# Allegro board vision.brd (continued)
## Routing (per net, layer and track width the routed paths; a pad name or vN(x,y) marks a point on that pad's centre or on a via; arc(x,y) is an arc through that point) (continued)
MEMORY.RA8: length 228.6
  TOP w0.15: U5.66 68.44,104.04 69.4,105 69.4,107.86 69,108.26 69,109.5 69.4,109.9 70.5,109.9 ; v1(76.28,73.14) 73.04,73.14 71.14,75.04 71.14,85.08 70.1,86.11 70.1,87.7 71,88.6 71,109.4 70.5,109.9 ; v1(102.84,100.53) 102.84,102.01 U22.28 ; 70.5,109.9 70.5,113.1 70.66,113.25 v1(70.66,113.96) 73.7,117 75.13,117 75.88,116.25 75.88,114.13 75.2,113.45 75.2,112.51 77.12,110.59 77.12,108.16 78.42,106.86 78.42,104.27 79.06,103.63 U18.28 ; v1(102.7,87.1) 103.06,87.45 U21.28 ; U20.28 103.06,74.95 v1(102.4,74.3) 101.2,73.1 96.88,73.1 96.47,72.7 87.22,72.7 v1(86.14,73.78) ; U17.28 79.06,87.52 v1(78.83,87.3) ; U19.28 79.06,112.19 v1(79.28,111.97) ; U23.28 103.06,111.97 v1(102.54,111.46) ; U16.28 v1(79.06,74.55)
  BOTTOM w0.15: 81.06,74.55 81.83,73.78 v1(86.14,73.78) ; 81.06,74.55 81.6,75.09 81.6,82.3 81.17,82.73 78.83,82.73 ; 81.06,74.55 v1(79.06,74.55) ; v1(102.54,111.46) 103.1,110.9 103.1,101.5 102.84,101.24 v1(102.84,100.53) 102.84,99.82 103.1,99.56 103.1,88.21 102.7,87.81 v1(102.7,87.1) 102.7,84.14 103.6,83.24 103.6,79.06 102.4,77.86 v1(102.4,74.3) ; 78.83,82.73 v1(78.83,87.3) ; 78.83,82.73 78.44,82.73 76.1,80.39 76.1,74.02 76.28,73.85 v1(76.28,73.14) ; v1(79.28,111.97) 79.28,108.08 76.2,105 67.4,105 67,105.4 67,106.1 67.6,106.7 76.3,106.7 76.8,107.2 76.8,113.55 76.15,114.2 71.6,114.2 71.37,113.96 v1(70.66,113.96)
MEMORY.RA9: length 281.3
  TOP w0.15: U16.22 86.67,74.95 87.03,74.6 v1(88.28,74.6) ; U20.22 110.67,76.61 109.88,77.41 106.39,77.41 106.23,77.25 106.23,75.16 106.13,75.06 106.13,73.88 107.78,72.23 111.24,72.23 111.86,71.61 v1(116.1,71.61) ; U5.65 v1(68.91,102.77) ; U22.22 110.67,101.56 111.28,100.95 112.26,100.95 112.58,101.28 112.58,106.85 112.47,106.97 ; U19.22 v1(86.67,111.97) ; v1(87.1,86.1) 87.1,87.41 86.67,87.83 U17.22 86.67,90.48 86.45,90.7 81.96,90.7 80.96,91.71 80.96,93.86 81.08,93.97 81.08,95.67 v1(86,100.6) 86.67,101.28 U18.22 ; U23.22 110.67,115.61 111.47,116.41 112.34,116.41 112.58,116.16 112.58,114.14 112.47,114.03 112.47,106.97 ; 112.47,106.97 115.75,106.97 v1(116.49,107.7) 117.26,107.7 118.2,106.76 118.2,88.6 117.5,87.9 116.6,87.9 116.4,88.1 116.4,90.15 115.75,90.8 110.99,90.8 110.67,90.48 U21.22
  BOTTOM w0.15: v1(68.91,102.77) 71.69,99.99 71.71,99.99 72.1,99.6 80.13,99.6 80.4,99.87 80.89,99.87 82.42,101.4 84.49,101.4 85.29,100.6 v1(86,100.6) 87.19,101.8 87.19,110.63 86.67,111.15 v1(86.67,111.97) ; v1(116.49,107.7) 116.49,98.77 115.8,98.08 115.8,95.7 116.1,95.4 116.1,90.14 117.1,89.14 117.1,85.08 116.64,84.62 116.64,77.84 116.1,77.3 v1(116.1,71.61) 116.1,64.37 114.03,62.3 113.2,62.3 112.8,61.9 74.1,61.9 72.1,63.9 72.1,66.5 72.5,66.9 93.4,66.9 93.9,67.4 93.9,70.8 93.11,71.59 91.29,71.59 v1(88.28,74.6) 89.4,75.72 89.4,84.7 88,86.1 v1(87.1,86.1)
MEMORY.RA10: length 201.7
  TOP w0.15: v1(87.94,98.3) v1(87.94,100.6) U18.21 ; 111.42,109.47 108.43,109.47 108.2,109.7 99.86,109.7 99.56,109.99 v1(98.75,109.99) ; 111.42,109.47 v1(111.42,107.4) 111.42,104.59 111.94,104.08 U22.21 ; 111.42,109.47 111.94,109.99 U23.21 ; U21.21 111.94,82.75 110.04,80.85 110.04,78.75 110.95,77.84 v1(111.94,77.84) U20.21 ; v1(78.31,97.03) 78.31,93.97 78.42,93.86 78.42,88.25 78,87.83 78,86.95 78.88,86.07 79.12,86.07 v1(79.62,85.57) ; U5.64 64.6,101.36 v1(62.81,101.36) ; U19.21 87.94,113.6 v1(87.95,113.6) ; U16.21 87.94,77.48 87.72,77.7 85.77,77.7 84.77,78.71 84.77,80.75 86.22,82.2 87.61,82.2 87.75,82.06 v1(88.47,82.06) ; U17.21 v1(87.94,84.9)
  BOTTOM w0.15: 78.31,98.38 80.78,98.38 81.08,98.67 86.86,98.67 87.23,98.3 v1(87.94,98.3) ; 78.31,98.38 v1(78.31,97.03) ; 78.31,98.38 65.79,98.38 v1(62.81,101.36) ; v1(87.94,100.6) 87.94,113.6 v1(87.95,113.6) 88.74,114.4 91.1,114.4 92.81,112.68 92.81,105.74 95.05,103.5 97.9,103.5 99,104.6 99,109.03 98.75,109.28 v1(98.75,109.99) ; v1(88.47,82.06) 87.94,82.58 v1(87.94,84.9) 87.23,84.9 86.84,85.3 86.3,85.3 85.8,85.8 80.56,85.8 80.33,85.57 v1(79.62,85.57) ; v1(111.42,107.4) 111.42,103.35 114.25,100.52 114.25,92.81 114.6,92.45 114.6,85.09 113.8,84.29 113.8,72.12 113.31,71.63 112.07,71.63 111.7,72 111.7,73.2 111.21,73.69 111.21,77.11 v1(111.94,77.84)
MEMORY.RA11: length 172.7
  TOP w0.15: U16.20 89.22,73.69 89.9,73 91.49,73 94.67,76.18 v1(94.67,82.43) 94.17,82.93 94.17,98.48 92.39,100.26 92.39,103.21 91.89,103.7 89.23,103.7 v1(89.22,103.69) U18.20 ; U19.20 v1(89.22,112.14) 90.62,110.73 99.77,110.73 100.3,110.2 102.72,110.2 103.92,111.4 109.1,111.4 110.04,112.34 110.04,116.23 110.81,117 112.71,117 113.22,116.5 U23.20 v1(113.22,108.43) ; U22.20 v1(113.22,98.26) ; U5.63 v1(67.05,100.23) ; v1(92.7,82.43) 92.7,83.47 89.22,86.96 U17.20 ; U20.20 113.22,77.72 113.85,78.36 113.85,80.81 113.78,80.87 v1(113.78,87.53) 113.22,88.1 U21.20
  BOTTOM w0.15: v1(89.22,112.14) v1(89.22,103.69) 89.22,100.71 88.07,99.57 80.77,99.57 80.4,99.2 68.08,99.2 v1(67.05,100.23) ; v1(113.78,87.53) 113.78,97.69 v1(113.22,98.26) 110.6,100.88 110.6,107.7 111.33,108.43 v1(113.22,108.43) ; v1(92.7,82.43) v1(94.67,82.43)
MEMORY.RA12: length 195.6
  TOP w0.15: 118.28,85.57 116.23,85.57 114.7,87.1 114.7,87.73 114.48,87.95 U21.19 ; 118.28,85.57 118.4,85.45 118.4,75.99 117.01,74.6 v1(115.1,74.6) 115.1,74.6 114.84,74.6 114.48,74.95 U20.19 ; 118.28,85.57 118.88,86.17 118.88,107.12 115.58,110.43 v1(114.48,110.43) U23.19 ; U19.19 v1(90.48,113.6) ; U5.62 66.86,98.96 67.88,99.98 v1(67.88,101.06) ; 92.37,86.8 93.55,85.63 93.55,78.7 v1(93.01,78.16) ; 92.37,86.8 90.95,86.8 90.48,87.27 U17.19 ; 92.37,86.8 92.39,86.82 92.39,96.25 90.48,98.15 v1(90.48,99.23) U18.19 ; v1(90.81,73.87) 90.81,74.73 90.48,75.06 U16.19 ; U22.19 v1(114.48,103.84)
  BOTTOM w0.15: v1(115.1,74.6) 115.1,63.82 113.88,62.6 98,62.6 95.8,64.8 95.8,71.4 93.33,73.87 v1(90.81,73.87) 90.81,78.66 91.32,79.17 92,79.17 v1(93.01,78.16) ; v1(67.88,101.06) 66.53,101.06 66.02,100.55 66.02,99.18 66.4,98.8 80.6,98.8 81.04,99.23 v1(90.48,99.23) 90.48,103.92 89.98,104.42 89.98,110.78 90.48,111.28 v1(90.48,113.6) ; v1(114.48,103.84) v1(114.48,110.43)
MEMORY.RA13: length 165.8
  TOP w0.15: U17.18 91.75,90.5 91.07,91.19 v1(89.69,91.19) 89.69,91.19 89.75,91.25 89.75,94.35 89.6,94.5 89.6,100.95 89.75,101.1 89.75,103.08 90.08,103.41 90.95,103.41 91.75,102.61 U18.18 91.75,98.21 v1(91.97,97.99) 93.84,96.12 93.84,77.91 93.34,77.41 92.56,77.41 91.75,76.61 U16.18 ; U20.18 v1(115.75,78.14) ; U22.18 115.68,102.14 v1(115.68,100.6) ; U23.18 v1(115.75,111.84) ; v1(116.19,87.2) 115.75,87.64 U21.18 ; U5.61 66.35,97.69 68.76,95.28 v1(68.76,92.6) ; v1(108.73,112.27) 104.34,112.27 103.58,113.03 103.58,114.03 103.69,114.14 103.69,116.16 103.45,116.41 92.56,116.41 91.75,115.61 U19.18 v1(91.75,112.66)
  BOTTOM w0.15: v1(108.73,112.27) 115.33,112.27 v1(115.75,111.84) 115.75,109.56 115.1,108.9 115.1,107.1 115.68,106.52 v1(115.68,100.6) 115.68,98.38 115.4,98.11 115.4,95.5 115.78,95.12 115.78,88.43 116.19,88.02 v1(116.19,87.2) 116.19,78.57 v1(115.75,78.14) ; v1(91.75,112.66) 91.97,112.44 v1(91.97,97.99) ; v1(68.76,92.6) 84,92.6 85.41,91.19 v1(89.69,91.19)
MEMORY.RA14: length 224.3
  TOP w0.15: v1(117.07,63.67) 116.05,63.67 115.45,64.27 ; v1(91.22,107.4) 91.75,106.86 U19.15 ; U21.15 115.75,81.25 116.73,82.23 v1(117.55,82.23) ; v1(97.02,65.59) 100.91,65.59 101.15,65.84 101.15,67.85 101.1,67.91 101.1,69.56 100.27,70.39 92.49,70.39 v1(91.75,69.66) U16.15 ; U20.15 115.75,64.57 115.45,64.27 ; U5.60 64.94,96.23 v1(66.69,96.23) 67.7,95.22 67.7,92.5 68,92.2 68.03,92.2 68.4,91.83 68.4,90.6 68.03,90.23 v1(68.03,89.17) ; 115.45,64.27 v1(112.11,64.27) ; v1(87.04,83.52) 87.75,83.52 87.83,83.6 91.5,83.6 91.9,83.2 91.9,81.09 91.75,80.94 U17.15 ; U18.15 91.75,95.69 v1(91.22,96.23) ; U22.15 115.75,94.05 116.31,94.6 v1(117.3,94.6) 117.3,95.48 117.84,96.03 117.84,103.03 115.75,105.11 U23.15
  BOTTOM w0.15: v1(68.03,89.17) 68.03,81.87 68.43,81.47 68.43,71.57 72.5,67.5 92.9,67.5 93.3,67.9 93.3,69.1 92.74,69.66 v1(91.75,69.66) 90.8,68.7 87.44,68.7 86.9,69.24 86.9,79.9 85.8,81 85.8,82.28 v1(87.04,83.52) ; v1(117.07,63.67) 117.07,72 116.4,72.67 116.4,77 117.07,77.67 117.07,81.75 v1(117.55,82.23) 118.05,82.73 118.05,93.85 v1(117.3,94.6) ; v1(97.02,65.59) 99.02,63.6 110.63,63.6 111.3,64.27 v1(112.11,64.27) ; v1(66.69,96.23) v1(91.22,96.23) 91.22,97.1 91.1,97.22 91.1,98.58 91.5,98.98 91.5,104.2 91.22,104.48 v1(91.22,107.4)
MEMORY.RA15: length 219.7
  TOP w0.15: v1(93.55,100.6) 93.55,103.28 92.4,104.42 90.58,104.42 90.48,104.52 U19.14 ; v1(96.94,66.93) 95.61,65.59 90.48,65.59 ; U22.14 114.99,93.29 v1(114.99,94.56) 115.8,94.56 117.4,96.17 117.4,97.55 113.85,101.09 113.85,103.28 113.75,103.38 113.75,104.38 114.48,105.11 U23.14 ; v1(91.02,81.4) 90.48,80.86 U17.14 ; U21.14 114.48,80.95 v1(115,81.47) ; v1(71.54,69.52) 71.54,65.36 72.1,64.8 78.68,64.8 79.69,65.81 79.69,67.85 79.58,67.97 79.58,69.6 80.27,70.3 83.74,70.3 86.04,68 86.04,65.73 86.18,65.59 90.48,65.59 ; U5.58 66.34,93.88 67.29,92.93 v1(67.29,91.57) ; U20.14 114.27,66.57 v1(114.27,65.16) ; 90.48,65.59 U16.14 ; U18.14 v1(90.48,94.76)
  BOTTOM w0.15: v1(67.29,91.57) 69.77,91.57 69.9,91.7 71.69,91.7 ; v1(71.54,69.52) 71.54,70.23 71.69,70.38 71.69,91.7 ; 71.69,91.7 84.25,91.7 85.55,90.4 91.63,90.4 97,95.77 97,96.6 96.6,97 95.64,97 92.14,93.5 88.52,93.5 87.9,94.12 87.9,95 88.39,95.49 89.75,95.49 v1(90.48,94.76) 91.26,94.76 93.55,97.04 v1(93.55,100.6) ; 97.8,66.93 100.73,64 110.19,64 111.35,65.16 v1(114.27,65.16) 114.27,80.74 v1(115,81.47) 115,94.55 v1(114.99,94.56) ; 97.8,66.93 v1(96.94,66.93) ; 97.8,66.93 97.8,75.23 91.63,81.4 v1(91.02,81.4)
MEMORY.RCS0: length 57.5
  TOP w0.15: U17.6 v1(80.33,81.4) ; U5.51 60.66,84.96 69.94,75.69 69.94,65.26 70.9,64.3 79.11,64.3 80.33,65.52 U16.6 v1(80.33,69.27)
  BOTTOM w0.15: v1(80.33,81.4) 77.8,78.87 77.8,70.38 78.91,69.27 v1(80.33,69.27)
MEMORY.RCS1: length 78.4
  TOP w0.15: v1(61.64,90.73) 59.39,88.48 U5.50 ; v1(61.64,103.31) 63.01,104.67 68.27,104.67 68.63,105.03 68.9,105.3 68.9,107.53 68.63,107.8 68.63,113.22 73.4,118 77.8,118 78.42,117.38 78.42,114.16 78.6,113.98 78.6,112.98 78.2,112.58 78.2,110.3 78.79,109.71 78.79,109.69 80.33,108.16 U19.6 ; v1(80.33,94.4) U18.6
  BOTTOM w0.15: v1(61.64,103.31) 61.64,95 ; 61.64,95 65.92,95 66.52,94.4 v1(80.33,94.4) ; 61.64,95 v1(61.64,90.73)
MEMORY.RCS2: length 125.4
  TOP w0.15: v1(96.64,84.5) 98.5,82.64 98.5,80.97 98.61,80.86 98.61,78.73 98.75,78.59 103.53,78.59 104.33,79.39 U21.6 ; U5.49 58.12,85.63 60.79,82.97 62.14,82.97 69.64,75.47 69.64,64.56 70.4,63.8 73.05,63.8 74.05,62.8 v1(94.89,62.8) 108.68,62.8 110.4,64.52 110.4,65.1 109.9,65.59 109.02,65.59 108.77,65.84 108.77,67.72 108.53,67.97 105.12,67.97 104.33,67.16 U20.6
  BOTTOM w0.15: v1(96.64,84.5) 91,84.5 89.8,83.3 89.8,73.7 91.01,72.49 94.01,72.49 95.5,71 95.5,64.22 94.89,63.61 v1(94.89,62.8)
MEMORY.RCS3: length 178.2
  TOP w0.15: U5.48 56.85,85.66 60.74,81.77 61.23,81.77 68.73,74.27 68.73,52.87 71.14,50.45 115.64,50.45 117.8,52.61 v1(117.8,64.84) ; U23.6 v1(104.33,108.22) ; v1(117.2,91) 116.49,91 116.33,91.16 111.92,91.16 111.31,91.77 111.31,93.84 111.41,93.94 v1(111.41,95.68) ; U22.6 v1(104.33,94.4)
  BOTTOM w0.15: v1(104.33,94.4) 104.33,95.68 ; 104.33,95.68 103.9,96.11 103.9,98.53 106,100.63 106,107.7 105.48,108.22 v1(104.33,108.22) ; 104.33,95.68 v1(111.41,95.68) ; v1(117.8,64.84) 117.8,65.65 117.5,65.96 117.5,72.1 116.8,72.8 116.8,76.8 118.4,78.4 118.4,94.99 117.88,95.51 116.91,95.51 116.5,95.1 116.5,94.1 117.2,93.4 v1(117.2,91)
MEMORY.RD0: length 179.5
  TOP w0.15: U22.7 v1(105.59,94.4) 103.59,96.4 97.9,96.4 96.9,95.4 95.9,95.4 95.4,95.9 95.4,97.2 96.2,98 v1(99.1,98) ; U16.7 81.59,65.32 82.81,64.1 104.53,64.1 v1(105.59,65.16) U20.7 ; U5.81 55.58,117.34 56.74,118.5 84.5,118.5 85,118 85,116.51 84.77,116.28 84.77,114.16 84.87,114.06 84.87,106.94 84.77,106.84 84.77,104.85 84.88,104.73 84.88,104.73 85.02,104.59 86.77,104.59 87.31,104.06 87.31,101.14 87.01,100.84 87.01,99.01 86.4,98.4 85.1,98.4 81.59,94.9 U18.7 81.59,92.39 82.4,91.59 88.37,91.59 88.69,91.92 v1(88.69,94.4)
  BOTTOM w0.15: v1(105.59,94.4) 105.59,87.63 v1(104.4,86.44) 105.14,85.7 108.92,85.7 108.92,85.7 110.14,85.7 110.95,84.88 110.95,82.63 103.59,75.27 103.59,67.16 v1(105.59,65.16) ; v1(99.1,98) 99.1,101.6 97.6,103.1 96.2,103.1 94.58,101.48 94.58,97.58 90.89,93.89 89.2,93.89 v1(88.69,94.4)
MEMORY.RD1: length 145.5
  TOP w0.15: v1(62.67,96.96) 54.2,105.43 54.2,114.15 54.31,114.26 U5.82 ; v1(82,69) 82.73,68.27 85.19,68.27 85.41,68.05 U16.10 85.41,65.5 86.4,64.5 102.42,64.5 103.69,65.77 103.69,67.87 104.08,68.27 109.19,68.27 109.41,68.05 U20.10 ; v1(75.98,85.96) 75.98,86.67 75.78,86.87 v1(75.78,95.49) ; U22.10 109.41,94.65 107.35,96.7 97.41,96.7 96.91,96.2 v1(96.2,96.2) ; U18.10 85.41,95.49 v1(85.41,95.49)
  BOTTOM w0.15: v1(96.2,96.2) 93.1,93.1 87.8,93.1 87.41,93.49 87.41,94.7 86.62,95.49 v1(85.41,95.49) 83.41,95.49 83.3,95.6 82.4,95.6 82.29,95.49 v1(75.78,95.49) 64.14,95.49 v1(62.67,96.96) ; v1(82,69) 81.29,69 80.69,68.4 79.11,68.4 75.4,72.11 75.4,80.4 76.1,81.1 76.1,85.13 75.98,85.25 v1(75.98,85.96)
MEMORY.RD2: length 200.4
  TOP w0.15: U5.83 v1(53.04,112.04) ; v1(109.6,99.53) 109.41,99.73 U22.23 ; v1(112.98,72.66) 110.28,72.66 v1(109.41,73.54) U20.23 ; U16.23 85.41,75 85.2,74.8 85.2,73.6 85.59,73.22 85.62,73.22 86.43,72.4 96.6,72.4 97,72.8 101.5,72.8 101.77,73.07 v1(104.69,73.07) ; v1(104.33,116.84) 103.1,116.84 102.97,116.7 100.5,116.7 100.37,116.84 87.41,116.84 86.97,116.41 86.27,116.41 85.92,116.06 v1(85.92,113.43) ; v1(84.03,113.43) 84.03,111.54 82.1,109.61 82.1,106.97 82.23,106.84 82.23,104.75 83.48,103.5 84.79,103.5 85.41,102.89 U18.23
  BOTTOM w0.15: v1(109.41,73.54) 108.94,73.07 v1(104.69,73.07) ; v1(85.92,113.43) v1(84.03,113.43) ; v1(53.04,112.04) 46.96,112.04 45.6,113.4 45.6,114.35 49.98,118.73 102.44,118.73 v1(104.33,116.84) 105.4,115.76 105.4,112.8 103.7,111.1 103.7,110.1 104.54,109.26 107.7,109.26 109.6,107.35 v1(109.6,99.53) 110.41,99.53 113,96.95 113,85.5 113.2,85.3 113.2,73.6 112.98,73.38 v1(112.98,72.66)
MEMORY.RD3: length 178.3
  TOP w0.15: v1(98.05,107.4) 99.26,107.4 99.88,106.78 99.88,104.83 101.15,103.56 101.15,101.1 102.94,99.31 v1(105.79,99.31) 105.59,99.51 U22.26 ; U18.26 81.59,103.48 81.24,103.84 v1(80.31,103.84) ; U20.26 105.59,72.59 105.3,72.3 ; 105.3,72.3 106.83,70.77 116.56,70.77 116.9,71.1 116.9,72.17 115.67,73.4 113.8,73.4 112.73,74.47 v1(111.96,74.47) ; 105.3,72.3 103.42,72.3 103.22,72.5 97.2,72.5 96.8,72.1 84.27,72.1 81.59,74.78 U16.26 ; U5.84 v1(51.77,104.78)
  BOTTOM w0.15: v1(51.77,104.78) 52.48,104.78 52.61,104.9 66.8,104.9 67.13,104.57 76.3,104.57 76.58,104.85 79.9,104.85 ; v1(80.31,103.84) 80.31,104.45 80.06,104.7 80.05,104.7 79.9,104.85 ; 79.9,104.85 79.9,111.2 81.9,113.2 81.9,113.44 83.16,114.7 91.27,114.7 93.11,112.86 93.11,105.86 95.17,103.8 97.6,103.8 98.3,104.5 98.3,106.44 98.05,106.69 v1(98.05,107.4) ; v1(111.96,74.47) 112.75,75.25 112.75,85.2 112.6,85.35 112.6,96.18 110.11,98.67 106.43,98.67 v1(105.79,99.31)
MEMORY.RD4: length 171.8
  TOP w0.15: U21.7 v1(105.59,81.4) ; U17.7 81.59,81.05 83.25,82.7 87.51,82.7 87.81,83 89.3,83 89.51,82.79 v1(91.02,82.79) ; U5.1 v1(50.5,113.07) ; U19.7 81.59,112.29 79.69,114.19 79.69,116.23 79.16,116.76 v1(79.16,117.57) ; U23.7 105.59,106.95 v1(105.15,107.4)
  BOTTOM w0.15: v1(50.5,113.07) 49.79,113.07 49.72,113 46.43,113 45.9,113.53 45.9,114.18 50.15,118.43 79.16,118.43 ; 79.16,118.43 102.01,118.43 103.4,117.03 103.4,107.6 103.6,107.4 ; 79.16,118.43 v1(79.16,117.57) ; 103.6,107.4 103.6,99.71 103.4,99.51 103.4,88.5 103.59,88.31 103.59,87.3 103.6,87.29 103.6,84.36 105.59,82.37 v1(105.59,81.4) 105.59,79.59 103.3,77.3 103.3,75.41 103.29,75.4 103.29,69.39 101.31,67.4 98.8,67.4 98.1,68.09 98.1,75.71 v1(91.02,82.79) ; 103.6,107.4 v1(105.15,107.4)
MEMORY.RD5: length 268.6
  TOP w0.15: U17.10 85.41,79.11 86.38,78.14 v1(91.84,78.14) ; U5.2 v1(49.23,109.47) ; U23.10 109.41,107.61 107.81,109.2 94.92,109.2 v1(94.13,109.99) 88.35,109.99 85.41,107.05 U19.10 ; v1(96.94,75.03) 98.37,75.03 98.61,75.28 98.61,77.19 99.13,77.7 108.59,77.7 109.41,78.52 U21.10 ; v1(113.62,63.44) v1(113.62,61.33)
  BOTTOM w0.15: 96.1,75.03 96.1,65.1 98,63.2 112.67,63.2 112.91,63.44 v1(113.62,63.44) ; 96.1,75.03 94.03,77.1 92.88,77.1 v1(91.84,78.14) ; 96.1,75.03 v1(96.94,75.03) ; v1(49.23,109.47) 50.44,109.47 50.74,109.17 ; 50.74,109.17 50.74,102.97 59.53,94.17 59.53,79.19 62.83,75.89 65.09,75.89 67.4,73.59 67.4,67.5 73.57,61.33 v1(113.62,61.33) ; 50.74,109.17 54.93,109.17 56.08,110.31 56.08,114.09 57.48,115.5 97.1,115.5 98.05,114.55 98.05,112.59 97.3,111.84 97.3,106.6 97.8,106.1 97.8,104.5 97.5,104.2 95.2,104.2 94.13,105.27 v1(94.13,109.99)
MEMORY.RD6: length 143.7
  TOP w0.15: v1(85.4,87.3) 85.4,88.05 85.41,88.06 U17.23 ; U5.3 v1(47.96,113.81) ; U19.23 85.41,116.45 v1(86.16,117.2) 87.36,118.4 107.53,118.4 109.41,116.53 U23.23 ; v1(100.22,95.56) 101.15,94.63 101.15,91.78 101.92,91 108.9,91 109.41,90.5 U21.23
  BOTTOM w0.15: v1(85.4,87.3) 85.4,88.01 85.89,88.5 90.2,88.5 91.1,87.6 96.79,87.6 99.96,90.78 99.96,92.53 99.4,93.09 99.4,95.56 ; v1(47.96,113.81) 49.99,115.83 84.79,115.83 v1(86.16,117.2) 98.2,117.2 99.5,115.9 99.5,108.6 99.4,108.5 99.4,99.5 100.1,98.8 100.1,97.4 99.4,96.7 99.4,95.56 ; 99.4,95.56 v1(100.22,95.56)
MEMORY.RD7: length 170.7
  TOP w0.15: v1(81,87.3) 81.59,87.89 U17.26 ; U5.4 v1(46.69,113.81) ; U19.26 v1(81.59,116.84) ; v1(101.81,117.57) 102.52,117.57 102.75,117.8 104.9,117.8 105.59,117.11 U23.26 ; v1(102.75,82.64) 103.83,82.64 105.59,84.41 U21.26
  BOTTOM w0.15: v1(46.69,113.81) 49.18,116.3 81.06,116.3 v1(81.59,116.84) 82.86,118.1 100.47,118.1 101,117.57 v1(101.81,117.57) 101.81,116.86 101.6,116.65 101.6,110.2 102.5,109.3 102.5,101.7 102,101.2 102,98.04 102.6,97.44 102.6,91.55 101.9,90.85 101.9,83.49 v1(102.75,82.64) 102.75,80.14 101.5,78.89 101.5,73.81 102.9,72.41 102.9,69.44 101.16,67.7 98.97,67.7 98.4,68.27 98.4,76.55 95.1,79.85 95.1,81.03 97.5,83.43 97.5,84.77 96.74,85.53 90.9,85.53 89.43,87 86.8,87 85.9,86.1 82.2,86.1 v1(81,87.3)
MEMORY.RWE: length 213
  TOP w0.15: 110.95,96.63 110.5,96.18 110.5,94.12 110.67,93.94 U22.11 ; 110.95,96.63 v1(116.6,96.63) ; 110.95,96.63 110.95,100.17 110.04,101.08 110.04,103.3 110.16,103.41 110.16,104 ; 88.48,106.97 88.58,106.87 88.58,104.38 88.4,104.2 88.4,103.38 88.48,103.3 88.48,101.38 88.83,101.03 88.84,101.03 89.1,100.78 89.1,97.3 88.42,96.62 88.38,96.62 v1(86.38,94.61) 86.38,93.08 U18.11 ; 88.48,106.97 87.19,106.97 86.67,106.44 U19.11 ; 88.48,106.97 90.42,108.9 102.5,108.9 103.69,107.71 103.69,104.81 104.21,104.3 109.86,104.3 110.16,104 ; 110.16,104 110.67,104.52 U23.11 ; U16.11 86.67,68.39 v1(87.77,69.49) ; v1(86.67,81.4) U17.11 ; U21.11 110.67,79.11 111.19,78.59 112.27,78.59 112.69,78.17 112.69,77.41 112.58,77.3 112.58,75.21 112.99,74.8 113.03,74.8 114.13,73.7 v1(117.7,73.7) 117.7,72.63 117.37,72.3 117.37,71.14 114.2,67.97 111.47,67.97 110.67,67.16 U20.11 ; U5.56 v1(62.81,91.34)
  BOTTOM w0.15: 65.96,91.34 65.96,83.2 67.98,81.18 67.98,71.52 72.3,67.2 93.1,67.2 93.6,67.7 93.6,69.7 92.7,70.6 87.77,70.6 ; 65.96,91.34 68.12,93.5 85.27,93.5 v1(86.38,94.61) ; 65.96,91.34 v1(62.81,91.34) ; 87.77,70.6 v1(87.77,69.49) ; 87.77,70.6 87.47,70.9 87.47,80.6 v1(86.67,81.4) ; v1(116.6,96.63) 117.62,96.63 118.8,95.45 118.8,74.8 v1(117.7,73.7)
MRD: length 49.4
  BOTTOM w0.15: J1.46 13.17,53.52 13.59,53.1 40.1,53.1 43.1,56.1 43.1,68.92 U2.9
MWR: length 53.8
  BOTTOM w0.15: J1.45 10.7,52.36 10.7,56.16 11.91,57.37 16.95,57.37 17.58,58 38.52,58 42.14,61.61 42.14,70.5 U2.10
N00036_DATA_DAAMP: length 46.6
  TOP w0.15: U10.5 v1(84.5,45.41) 84.5,43.51 83.66,42.67 ; 83.66,38.86 83.66,42.67 ; 83.66,38.86 U8.5 ; 83.66,38.86 85.78,38.86 93.88,30.77 L4.2 ; 83.66,42.67 U8.8
  BOTTOM w0.15: L4.2 91.95,31.93 91.95,33.71 89.66,36 R7.1 ; R6.1 89.72,38.5 90.05,38.83 90.05,43.75 88.4,45.41 v1(84.5,45.41)
N00036_DATA_DAAMP1: length 44.2
  TOP w0.15: 83.97,19.24 83.97,22.75 ; 83.97,19.24 86.38,19.24 88.9,16.73 93.83,16.73 95,15.56 95,11.2 L6.2 ; 83.97,19.24 83.66,18.94 U11.5 ; 83.97,22.75 U11.8 ; 83.97,22.75 v1(83.97,23.68) 83.97,24.71 84.73,25.48 U13.5
  BOTTOM w0.15: v1(83.97,23.68) 84.67,23.68 84.8,23.8 88.92,23.8 89.67,23.04 89.67,18.58 ; 89.67,18.58 89.67,16.7 89.06,16.08 R9.1 ; 89.67,18.58 R8.1
N00038_DATA_DAAMP: length 19.9
  TOP w0.15: v1(85.89,37.59) U8.4 v1(79.11,37.59)
  BOTTOM w0.15: C8.1 77.5,37.14 77.62,37.02 78.53,37.02 v1(79.11,37.59) ; L3.2 93.88,32.77 89.38,37.27 86.21,37.27 v1(85.89,37.59)
N00038_DATA_DAAMP1: length 22.3
  TOP w0.15: L5.2 87.9,12.58 v1(84.1,16.38) 84.1,17.19 83.62,17.67 U11.4
  BOTTOM w0.15: C11.1 77.5,17.17 78.29,16.38 v1(84.1,16.38)
N00044_DATA_DAAMP: length 6.1
  TOP w0.15: U10.1 92.56,41.59 94.22,39.93 U9.2
N00044_DATA_DAAMP1: length 6.1
  TOP w0.15: U13.1 92.56,21.67 94.22,20.01 96.43,20.01
N00060_DATA_DAAMP: length 43.8
  TOP w0.15: U8.6 80.54,40.14 77.75,37.34 77.75,30.8 79.65,28.9 97.67,28.9 97.79,29.02 v1(98.5,29.02)
  BOTTOM w0.15: U9.3 v1(98.5,29.02)
N00060_DATA_DAAMP1: length 25.7
  TOP w0.15: U11.6 81.44,20.21 80.82,19.6 80.82,18.54 81.05,18.31 85.38,18.31 87.99,15.7 v1(92.38,15.7)
  BOTTOM w0.15: U12.3 98.5,17.91 94.42,13.83 93.44,13.83 92.38,14.88 v1(92.38,15.7)
N282866_DATA_DAAMP: length 4
  TOP w0.15: v1(86.19,40.21) 86.03,40.38 U10.8
  BOTTOM w0.15: v1(86.19,40.21) 86.19,38.59 86.28,38.5 R6.2
N282866_DATA_DAAMP1: length 3.6
  TOP w0.15: U13.8 86.03,20.59 v1(86.33,20.29)
  BOTTOM w0.15: R8.2 86.94,18.58 86.33,19.2 v1(86.33,20.29)
N282912_DATA_DAAMP: length 12.6
  TOP w0.15: v1(89.02,42.63) 89.25,42.87 U10.2
  BOTTOM w0.15: v1(89.02,42.63) 87.53,42.63 84.86,39.96 84.86,37.4 86.26,36 R7.2
N282912_DATA_DAAMP1: length 12
  TOP w0.15: U13.2 v1(88.72,22.94)
  BOTTOM w0.15: v1(88.72,22.94) 87.88,22.94 85.5,20.57 85.5,16.86 86.28,16.08 R9.2
NCS: length 18.9
  TOP w0.15: U5.11 v1(37.8,118.05)
  BOTTOM w0.15: v1(37.8,118.05) 29,109.25 U7.4
OE: length 19.3
  TOP w0.15: U5.32 35.27,88.8 34.7,89.38 34.7,91.62 30.86,95.45 v1(29.33,95.45)
  BOTTOM w0.15: v1(29.33,95.45) 27.77,97.01 27.77,101.36 U7.3
OUTA: length 16.8
  TOP w0.15: L1.1 98.2,35 102.8,39.6 102.8,43.06 101.8,44.07 U9.6
OUTB: length 18
  BOTTOM w0.15: U12.6 100.57,25.38 99.24,26.7 97.3,26.7 94,23.4 L2.1
Q0: length 8.5
  TOP w0.15: U6.18 73.5,60.17 73.67,60 R1.1
Q1: length 8.4
  TOP w0.15: U6.16 73.41,57.63 73.55,57.5 R2.1
Q2: length 8.4
  TOP w0.15: R3.1 73.51,55 73.41,55.09 U6.14
Q3: length 8.4
  TOP w0.15: R4.1 73.47,52.5 73.41,52.55 U6.12
RDY: length 49.9
  BOTTOM w0.15: U2.23 22.34,54.04 21.59,54.79 11.83,54.79 11,53.96 11,53.15 11.86,52.29 12.6,52.29 13.39,51.5 13.39,50.86 12.4,49.86 11.67,49.86 10.17,51.36 10.17,61.77 J1.50
RESET: length 54.8
  TOP w0.15: U5.15 32.36,110.39 24.86,102.9 v1(24.86,88.54)
  BOTTOM w0.15: J1.53 15.24,71.3 19.3,75.36 19.3,85.66 22.19,88.54 v1(24.86,88.54)
SEL: length 40.9
  TOP w0.15: U5.13 v1(38.34,112.93)
  BOTTOM w0.15: U2.14 39.55,78.08 39.55,86.78 41.1,88.33 41.1,111 39.17,112.93 v1(38.34,112.93)
V+12: length 185.6
  TOP w0.4: U12.7 96.81,26.69 v1(90.97,26.69) U13.4 ; v1(66.4,73.11) v1(30.99,73.11) ; 94.05,47.01 v1(94.05,45.41) ; 94.05,47.01 91.98,47.01 90.97,46.01 U10.4 ; 94.05,47.01 96.41,47.01 U9.7 ; J1.64 J1.63
  BOTTOM w0.4: 91.28,28.65 90.97,28.35 v1(90.97,26.69) 90.97,13.83 90.72,13.58 C12.1 ; 91.28,28.65 94.46,28.65 95.35,29.54 95.35,36.5 94.05,37.8 v1(94.05,45.41) 92.95,46.51 79.09,46.51 66.4,59.21 66.4,67.48 66.4,67.49 v1(66.4,73.11) ; 91.28,28.65 91.28,32.99 90.77,33.5 C9.1 ; J1.63 18.37,96.7 26.51,88.56 26.51,76.16 28.23,74.44 28.23,74.42 29.12,73.53 29.14,73.53 29.56,73.11 v1(30.99,73.11)
VCLKA: length 82
  TOP w0.2: 67.83,46.42 72.24,46.42 72.84,45.83 U8.11 ; 67.83,46.42 67.83,73.68 60.97,80.54 44.02,80.54 39.07,85.49 U5.34 ; 67.83,46.42 67.83,34.59 68.63,33.78 U14.11
VCLKC: length 100.8
  TOP w0.2: U11.11 74.17,25.29 74.17,23.6 73.94,23.36 67.83,23.36 ; v1(67.83,29.51) 67.83,23.36 ; 67.83,23.36 67.82,23.35 67.82,14.47 68.44,13.86 U15.11
  BOTTOM w0.2: v1(67.83,29.51) 65.7,31.64 65.7,67.19 58.69,74.21 58.69,85.3 50.49,93.5 R5.2
VD0: length 88.8
  TOP w0.15: U5.39 45.42,85.59 48.85,82.17 v1(53.43,82.17) ; U6.2 v1(58.08,61.45) ; U14.2 v1(58.08,43.95) ; U15.2 v1(58.05,24.02)
  BOTTOM w0.15: v1(53.43,82.17) 53.43,66.1 v1(58.08,61.45) 58.08,55.8 57.8,55.52 57.8,45.08 58.08,44.8 v1(58.08,43.95) 58.08,30.03 58.05,30 ; 58.05,30 v1(58.05,24.02) ; 58.05,30 R13.2
VD1: length 98.4
  TOP w0.15: 54.78,42.38 55.08,42.67 U14.3 ; 54.78,42.38 v1(54.78,27) ; 54.78,42.38 48,49.15 48,57.67 v1(51.33,61.01) 52.17,60.17 U6.3 ; U15.3 v1(57.72,22.75) ; U5.40 46.69,85.18 48.47,83.4 v1(51.33,83.4)
  BOTTOM w0.15: v1(51.33,61.01) v1(51.33,83.4) ; v1(57.72,22.75) 54.78,25.7 v1(54.78,27) R17.2
VD2: length 116.1
  TOP w0.15: v1(47.96,85.21) U5.41 ; U15.4 57.84,21.48 57.16,20.8 57.16,20.13 57.72,19.57 61.01,19.57 61.2,19.38 61.2,18.5 61.01,18.31 60.96,18.31 60.95,18.3 52.98,18.3 52.39,17.71 51.47,17.71 49.82,19.36 49.82,22.77 v1(51.05,24) 53.07,24 56.3,27.23 56.3,39.79 56.38,39.86 v1(56.38,40.57) 57.21,41.41 U14.4 ; v1(56.38,58.91) U6.4
  BOTTOM w0.15: v1(47.96,85.21) 47.96,57.68 51.01,54.64 55.7,54.64 ; R12.2 v1(51.05,24) ; 55.7,54.64 55.7,58.23 v1(56.38,58.91) ; 55.7,54.64 56.3,54.04 56.3,41.36 56.38,41.28 v1(56.38,40.57)
VD3: length 99
  TOP w0.15: 61.99,39.84 61.7,40.14 U14.5 ; 61.99,39.84 62.1,39.73 62.1,21.11 61.2,20.21 U15.5 58.27,20.21 v1(58.04,20.45) ; 61.99,39.84 62.86,40.7 62.86,46.79 56.2,53.45 56.2,57.63 ; v1(49.23,85.21) U5.42 ; v1(49.23,57.63) 56.2,57.63 ; 56.2,57.63 U6.5
  BOTTOM w0.15: R16.2 57.49,21 v1(58.04,20.45) ; v1(49.23,57.63) v1(49.23,85.21)
VD4: length 94.5
  TOP w0.15: U15.6 56.76,18.94 ; 56.76,18.94 v1(51.45,18.94) ; 56.76,18.94 56.76,24.56 57.21,25.01 v1(57.21,38.86) U14.6 ; U6.6 v1(57.21,56.37) ; U5.43 v1(50.5,85.21)
  BOTTOM w0.15: v1(51.45,18.94) 50.51,18 R11.2 ; v1(57.21,38.86) 57.21,39.58 57.6,39.97 57.6,42.6 57.21,42.99 v1(57.21,56.37) 57.21,57.08 57.3,57.17 57.3,59.25 56.41,60.14 50.86,60.14 50.4,60.6 50.4,84.4 50.5,84.5 v1(50.5,85.21)
VD5: length 122.8
  TOP w0.15: v1(61.16,28.25) 61.2,28.28 61.2,37.58 61.17,37.59 U14.7 ; U6.7 64.17,55.09 64.19,55.08 v1(64.19,50.22) 64.19,21.2 v1(62.3,19.3) 62.3,18.59 61.38,17.67 U15.7 56.56,17.67 v1(53.89,15) ; U5.44 v1(51.77,90.78)
  BOTTOM w0.15: v1(61.16,28.25) 61.16,20.44 v1(62.3,19.3) ; v1(64.19,50.22) 63.23,51.19 63.23,63.31 57.46,69.08 57.46,85.09 v1(51.77,90.78) ; R15.2 v1(53.89,15)
VD6: length 99.1
  TOP w0.15: U6.8 v1(58.92,53.83) ; v1(58.92,29.88) 58.08,30.71 58.08,35.93 58.48,36.33 U14.8 ; U5.45 v1(53.04,83.83) ; U15.8 v1(58.05,16.4)
  BOTTOM w0.15: v1(53.04,83.83) 55.43,81.44 55.43,66.82 59,63.25 59,54.62 58.92,54.53 v1(58.92,53.83) 59.48,53.27 59.48,41.78 58.92,41.22 v1(58.92,29.88) 58.92,17.27 v1(58.05,16.4) 53.65,12 R10.2
VD7: length 104.7
  TOP w0.15: U6.9 v1(61.2,52.55) ; v1(60.33,31.56) 59.37,31.56 58.48,32.45 58.48,35.03 58.51,35.05 U14.9 ; U5.46 v1(54.31,85.06) ; U15.9 v1(63.26,15.13)
  BOTTOM w0.15: v1(54.31,85.06) 56.66,82.71 56.66,67.88 61.2,63.34 v1(61.2,52.55) 61.2,31.56 ; 61.2,31.56 v1(60.33,31.56) ; 61.2,31.56 63.26,29.49 v1(63.26,15.13) 57.13,9 R14.2
VREF: length 26.2
  TOP w0.15: L5.1 104.08,10 R18.1
  BOTTOM w0.15: L3.1 102.89,31.11 102.89,13.97 L5.1
WAIT: length 42.7
  TOP w0.15: v1(32.44,85.7) 33.99,87.25 U5.33
  BOTTOM w0.15: v1(32.44,85.7) 32.44,71.6 27.84,67 12.86,67 J1.51
WSTAT: length 53.4
  TOP w0.15: U6.11 70.81,51.28 69.04,53.06 69.04,74.87 61.54,82.36 60.89,82.36 57.48,85.77 57.48,88.45 61.65,92.61 U5.57
N14843: length 3.2
  BOTTOM w0.15: R16.1 C19.1
N14849: length 3.2
  BOTTOM w0.15: R12.1 C15.1
N14853: length 3.2
  BOTTOM w0.15: R17.1 C20.1
N14855: length 3.2
  BOTTOM w0.15: R13.1 C16.1
N15143: length 3.2
  BOTTOM w0.15: R14.1 C17.1
N15151: length 3.2
  BOTTOM w0.15: R10.1 C13.1
N15155: length 3.2
  BOTTOM w0.15: R15.1 C18.1
N15161: length 3.2
  BOTTOM w0.15: R11.1 C14.1
N58063: length 3.7
  TOP w0.15: U14.19 U8.12
N58118: length 3.7
  TOP w0.15: U14.18 U8.13
N58173: length 3.7
  TOP w0.15: U14.17 U8.14
N58228: length 3.7
  TOP w0.15: U14.16 U8.15
N58283: length 3.7
  TOP w0.15: U14.15 U8.16
N58338: length 3.7
  TOP w0.15: U14.14 U8.17
N58393: length 3.7
  TOP w0.15: U14.13 U8.18
N58448: length 3.7
  TOP w0.15: U14.12 U8.19
N58834: length 3.7
  TOP w0.15: U15.19 U11.12
N58889: length 3.7
  TOP w0.15: U15.18 U11.13
N58944: length 3.7
  TOP w0.15: U15.17 U11.14
N58999: length 3.7
  TOP w0.15: U15.16 U11.15
N59054: length 3.7
  TOP w0.15: U15.15 U11.16
N59109: length 3.7
  TOP w0.15: U15.14 U11.17
N59164: length 3.7
  TOP w0.15: U15.13 U11.18
N59219: length 3.7
  TOP w0.15: U15.12 U11.19
N409523: length 7.8
  TOP w0.15: v1(43.93,93.5) 42.88,92.45 U5.37
  BOTTOM w0.15: R5.1 v1(43.93,93.5)

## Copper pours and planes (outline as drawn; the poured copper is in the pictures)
GND on GND1: 21,1.41 21,9 20.41,10.41 19,11 1.41,11 1,11.41 1,108.59 1.41,109 19,109 20.41,109.59 21,111 21,118.59 21.41,119 118.59,119 119,118.59 119,1.41 118.59,1 21.41,1 ; 3 cut-outs
GND on GND2: 21,1.41 21,9 20.41,10.41 19,11 1.41,11 1,11.41 1,108.59 1.41,109 19,109 20.41,109.59 21,111 21,118.59 21.41,119 118.59,119 119,118.59 119,1.41 118.59,1 21.41,1 ; 3 cut-outs
VCC on VCC1, VCC2: 21,1.41 21,9 20.41,10.41 19,11 1.41,11 1,11.41 1,108.59 1.41,109 19,109 20.41,109.59 21,111 21,118.59 21.41,119 118.59,119 119,118.59 119,1.41 118.59,1 21.41,1 ; 2 cut-outs
